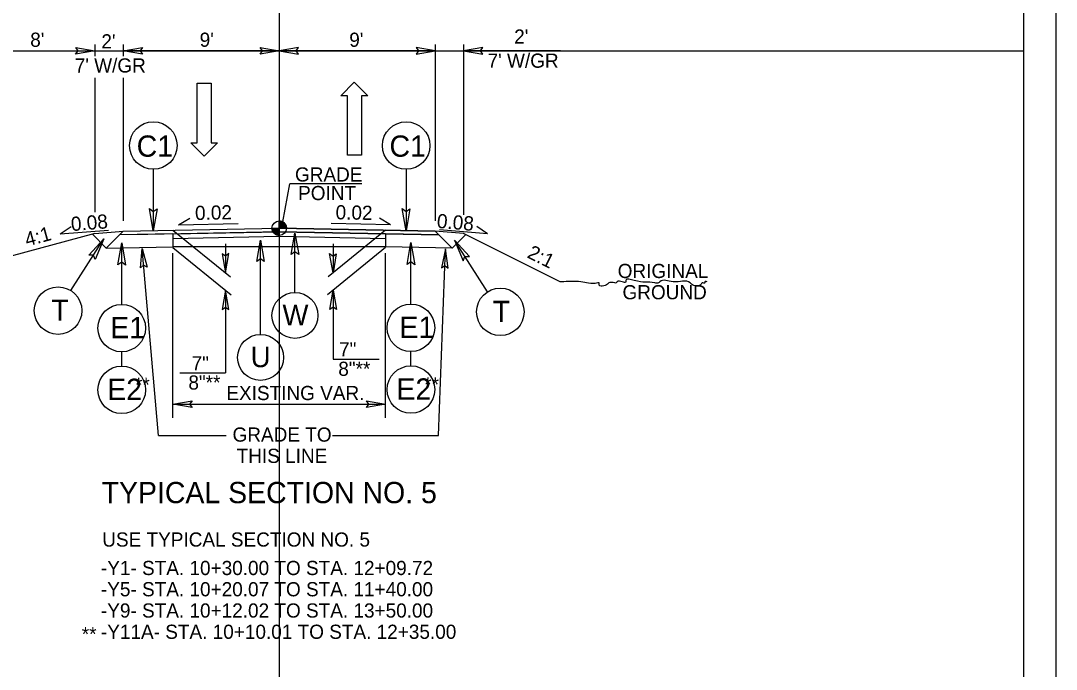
# Model space of a CAD drawing. Extents: x 18938 to 19565, y 6931 to 7973.
# Drawn here: x 19309.4 to 19382.4, y 7592.1 to 7637.9 of the extents above; entities that cross this region are included whole.
import ezdxf

# ---------------------------------------------------------------- set-up
doc = ezdxf.new("R2010")
doc.units = 0
for name, color, linetype in [('Old_Level_1', 7, 'Continuous'), ('Old_Level_11', 7, 'Continuous'), ('Old_Level_2', 7, 'Continuous'), ('Old_Level_3', 7, 'Continuous'), ('Prop Dimension', 7, 'Continuous'), ('Prop Pavement Schedule Description CELL', 7, 'Continuous'), ('Prop Shade Medium', 7, 'Continuous'), ('Prop Terminator CELL', 7, 'Continuous'), ('Sheet Data Field CELL', 7, 'Continuous'), ('Sheet Plot Border Outside CELL', 7, 'Continuous'), ('Sheet Typical CELL', 7, 'Continuous'), ('Typical Curb CELL', 7, 'Continuous'), ('Typical Detail Wedge1 CELL', 7, 'Continuous'), ('Typical Detail Wedge2 CELL', 7, 'Continuous'), ('Typical Detail Wedge3 CELL', 7, 'Continuous'), ('Typical Guardrail CELL', 7, 'Continuous'), ('Typical Hinge Slope Arterial CELL', 7, 'Continuous'), ('Typical ID Circle CELL', 7, 'Continuous'), ('Typical Pavement Slope Information CELL', 7, 'Continuous'), ('Typical Shoulder Slope Information CELL', 7, 'Continuous'), ('Typical Terminator CELL', 7, 'Continuous'), ('Typical Text General CELL', 7, 'Continuous'), ('Typical Text Grade Point CELL', 7, 'Continuous'), ('Typical Text ID Circle CELL', 7, 'Continuous')]:
    doc.layers.add(name, color=color, linetype=linetype)

msp = doc.modelspace()

# ---------------------------------------------------------------- linework, layer by layer
at = {"layer": 'Old_Level_1'}
for p, q in [((19320.158, 7622.846), (19327.659, 7622.996)), ((19327.659, 7622.996), (19335.158, 7622.846))]:
    msp.add_line(p, q, dxfattribs=at)
at = {"layer": 'Old_Level_3'}
msp.add_line((19314.658, 7635.752), (19316.658, 7635.752), dxfattribs=at)
at = {"layer": 'Prop Dimension'}
msp.add_lwpolyline([(19155.167, 7519.077), (19382.434, 7519.077), (19382.434, 7665.511), (19155.167, 7665.511)], close=True, dxfattribs=at)
at = {"layer": 'Prop Pavement Schedule Description CELL'}
for p, q in [((19315.468, 7621.836), (19314.484, 7622.82)), ((19314.658, 7622.866), (19316.658, 7623.026)), ((19315.468, 7621.836), (19316.658, 7623.026)), ((19320.158, 7622.846), (19316.403, 7622.771)), ((19316.658, 7623.026), (19327.659, 7623.246)), ((19338.658, 7623.026), (19327.658, 7623.246)), ((19335.158, 7622.846), (19338.913, 7622.771)), ((19340.658, 7622.866), (19338.658, 7623.026)), ((19339.849, 7621.836), (19338.658, 7623.026)), ((19339.849, 7621.836), (19340.806, 7622.793)), ((19347.46, 7619.466), (19340.658, 7622.866)), ((19315.468, 7621.836), (19320.158, 7621.93)), ((19320.158, 7621.934), (19320.158, 7621.93)), ((19335.158, 7621.934), (19335.158, 7621.93)), ((19339.849, 7621.836), (19335.158, 7621.93))]:
    msp.add_line(p, q, dxfattribs=at)
at = {"layer": 'Prop Shade Medium'}
msp.add_line((19314.658, 7622.866), (19306.658, 7620.717), dxfattribs=at)
at = {"layer": 'Sheet Data Field CELL'}
for points in [[(19313.308, 7635.984), (19314.658, 7635.752), (19313.301, 7635.512), (19313.473, 7635.752)], [(19313.308, 7635.984), (19314.658, 7635.752), (19313.301, 7635.512), (19313.473, 7635.752)], [(19318.008, 7635.519), (19316.658, 7635.752), (19318.016, 7635.992), (19317.843, 7635.752)], [(19326.313, 7635.984), (19327.663, 7635.752), (19326.305, 7635.512), (19326.478, 7635.752)], [(19329.013, 7635.984), (19327.663, 7635.752), (19329.02, 7635.512), (19328.848, 7635.752)], [(19337.308, 7635.519), (19338.658, 7635.752), (19337.301, 7635.992), (19337.473, 7635.752)], [(19342.008, 7635.984), (19340.658, 7635.752), (19342.016, 7635.512), (19341.843, 7635.752)], [(19317.88, 7620.452), (19317.996, 7621.817), (19318.352, 7620.485), (19318.098, 7620.636)], [(19323.635, 7621.442), (19323.868, 7620.092), (19324.108, 7621.449), (19323.868, 7621.277)], [(19331.682, 7621.442), (19331.449, 7620.092), (19331.209, 7621.449), (19331.449, 7621.277)], [(19339.559, 7620.433), (19339.377, 7621.791), (19339.087, 7620.443), (19339.333, 7620.607)], [(19324.1, 7617.518), (19323.867, 7618.868), (19323.627, 7617.511), (19323.867, 7617.683)], [(19331.217, 7617.518), (19331.449, 7618.868), (19331.689, 7617.511), (19331.449, 7617.683)], [(19321.508, 7610.596), (19320.158, 7610.829), (19321.516, 7611.069), (19321.343, 7610.829)], [(19333.808, 7611.061), (19335.158, 7610.829), (19333.801, 7610.589), (19333.973, 7610.829)]]:
    msp.add_lwpolyline(points, close=True, dxfattribs=at)
at = {"layer": 'Sheet Typical CELL'}
for p, q in [((19314.658, 7636.212), (19314.658, 7635.391)), ((19316.658, 7636.212), (19316.658, 7635.391)), ((19338.658, 7636.212), (19338.658, 7623.766)), ((19340.658, 7636.212), (19340.658, 7624.193)), ((19306.658, 7635.752), (19314.658, 7635.752)), ((19338.658, 7635.752), (19316.658, 7635.752)), ((19347.496, 7635.752), (19340.658, 7635.752)), ((19314.658, 7633.843), (19314.658, 7624.366)), ((19316.658, 7633.843), (19316.658, 7623.766)), ((19320.158, 7623.096), (19324.214, 7619.812)), ((19335.158, 7623.096), (19331.103, 7619.812)), ((19323.868, 7622.136), (19323.868, 7620.092)), ((19331.449, 7622.136), (19331.449, 7620.092)), ((19319.137, 7608.612), (19317.996, 7621.817)), ((19320.158, 7621.873), (19324.263, 7618.548)), ((19320.158, 7609.865), (19320.158, 7621.49)), ((19335.158, 7621.873), (19331.053, 7618.548)), ((19335.158, 7609.865), (19335.158, 7621.49)), ((19338.89, 7608.612), (19339.377, 7621.791)), ((19323.867, 7618.868), (19323.867, 7613.031)), ((19331.449, 7618.868), (19331.449, 7614)), ((19331.449, 7614), (19334.701, 7614)), ((19320.643, 7613.031), (19323.867, 7613.031)), ((19320.158, 7610.829), (19335.158, 7610.829)), ((19319.137, 7608.612), (19323.928, 7608.612)), ((19331.406, 7608.612), (19338.89, 7608.612))]:
    msp.add_line(p, q, dxfattribs=at)
at = {"layer": 'Typical Curb CELL'}
msp.add_spline([(19357.824, 7619.466), (19357.652, 7619.466), (19357.652, 7619.38), (19357.481, 7619.38), (19357.396, 7619.294), (19356.71, 7619.294), (19356.625, 7619.38), (19355.425, 7619.466), (19354.483, 7619.466), (19354.398, 7619.38), (19354.141, 7619.38), (19352.685, 7619.551), (19352.085, 7619.551), (19352.085, 7619.466), (19351.485, 7619.466), (19351.4, 7619.38), (19351.314, 7619.38), (19350.886, 7619.38), (19350.8, 7619.294), (19350.201, 7619.294), (19350.201, 7619.38), (19350.115, 7619.38), (19348.916, 7619.466), (19347.545, 7619.466), (19347.46, 7619.466)], degree=3, dxfattribs=at)
at = {"layer": 'Typical Detail Wedge1 CELL'}
for p, q in [((19327.659, 7623.246), (19327.659, 7623.758)), ((19327.146, 7623.246), (19327.659, 7623.246)), ((19327.658, 7622.734), (19327.659, 7623.246)), ((19327.659, 7623.246), (19327.658, 7622.734)), ((19328.17, 7623.246), (19327.659, 7623.246))]:
    msp.add_line(p, q, dxfattribs=at)
for points in [[(19327.663, 7623.758), (19327.663, 7623.758), (19327.663, 7623.246)], [(19327.674, 7623.758), (19327.673, 7623.246)], [(19327.684, 7623.758), (19327.684, 7623.246)], [(19327.694, 7623.757), (19327.694, 7623.246)], [(19327.704, 7623.756), (19327.704, 7623.246)], [(19327.715, 7623.755), (19327.715, 7623.246)], [(19327.725, 7623.754), (19327.725, 7623.246)], [(19327.735, 7623.753), (19327.735, 7623.246)], [(19327.746, 7623.751), (19327.745, 7623.246)], [(19327.756, 7623.749), (19327.756, 7623.246)], [(19327.766, 7623.747), (19327.766, 7623.246)], [(19327.776, 7623.744), (19327.776, 7623.246)], [(19327.787, 7623.742), (19327.786, 7623.246)], [(19327.797, 7623.739), (19327.797, 7623.246)], [(19327.807, 7623.736), (19327.807, 7623.246)], [(19327.817, 7623.733), (19327.817, 7623.246)], [(19327.828, 7623.73), (19327.827, 7623.246)], [(19327.838, 7623.726), (19327.837, 7623.246)], [(19327.848, 7623.722), (19327.848, 7623.246)], [(19327.858, 7623.718), (19327.858, 7623.246)], [(19327.868, 7623.713), (19327.868, 7623.246)], [(19327.878, 7623.709), (19327.878, 7623.246)], [(19327.889, 7623.704), (19327.889, 7623.246)], [(19327.899, 7623.698), (19327.899, 7623.246)], [(19327.909, 7623.693), (19327.909, 7623.246)], [(19327.919, 7623.687), (19327.919, 7623.246)], [(19327.93, 7623.681), (19327.93, 7623.246)], [(19327.94, 7623.674), (19327.94, 7623.246)], [(19327.95, 7623.667), (19327.95, 7623.246)], [(19327.961, 7623.66), (19327.961, 7623.246)], [(19327.971, 7623.652), (19327.971, 7623.246)], [(19327.981, 7623.644), (19327.981, 7623.246)], [(19327.991, 7623.635), (19327.991, 7623.246)], [(19328.002, 7623.626), (19328.001, 7623.246)], [(19328.012, 7623.617), (19328.012, 7623.246)], [(19328.022, 7623.607), (19328.022, 7623.246)], [(19328.032, 7623.596), (19328.032, 7623.246)], [(19328.042, 7623.585), (19328.042, 7623.246)], [(19328.053, 7623.573), (19328.052, 7623.246)], [(19328.063, 7623.56), (19328.063, 7623.246)], [(19328.073, 7623.547), (19328.073, 7623.246)], [(19328.083, 7623.532), (19328.083, 7623.246)], [(19328.093, 7623.516), (19328.093, 7623.246)], [(19328.104, 7623.499), (19328.104, 7623.246)], [(19328.114, 7623.48), (19328.114, 7623.246)], [(19328.124, 7623.458), (19328.124, 7623.246)], [(19328.135, 7623.435), (19328.135, 7623.246)], [(19327.149, 7623.246), (19327.149, 7623.19)], [(19327.16, 7623.246), (19327.16, 7623.13)], [(19327.17, 7623.246), (19327.17, 7623.093)], [(19327.18, 7623.246), (19327.18, 7623.063)], [(19327.19, 7623.246), (19327.19, 7623.038)], [(19327.2, 7623.246), (19327.2, 7623.017)], [(19327.211, 7623.246), (19327.211, 7622.997)], [(19327.221, 7623.246), (19327.221, 7622.98)], [(19327.231, 7623.246), (19327.231, 7622.964)], [(19327.242, 7623.246), (19327.242, 7622.949)], [(19327.252, 7623.246), (19327.252, 7622.935)], [(19327.262, 7623.246), (19327.262, 7622.922)], [(19327.272, 7623.246), (19327.272, 7622.91)], [(19327.283, 7623.246), (19327.283, 7622.898)], [(19327.293, 7623.246), (19327.293, 7622.888)], [(19327.303, 7623.246), (19327.303, 7622.878)], [(19327.313, 7623.246), (19327.313, 7622.868)], [(19327.324, 7623.246), (19327.323, 7622.859)], [(19327.334, 7623.246), (19327.334, 7622.85)], [(19327.344, 7623.246), (19327.344, 7622.842)], [(19327.354, 7623.246), (19327.354, 7622.835)], [(19327.364, 7623.246), (19327.364, 7622.827)], [(19327.375, 7623.246), (19327.374, 7622.82)], [(19327.385, 7623.246), (19327.385, 7622.813)], [(19327.395, 7623.246), (19327.395, 7622.807)], [(19327.405, 7623.246), (19327.405, 7622.801)], [(19327.415, 7623.246), (19327.415, 7622.795)], [(19327.426, 7623.246), (19327.426, 7622.79)], [(19327.436, 7623.246), (19327.436, 7622.785)], [(19327.446, 7623.246), (19327.446, 7622.78)], [(19327.457, 7623.246), (19327.457, 7622.776)], [(19327.467, 7623.246), (19327.467, 7622.772)], [(19327.477, 7623.246), (19327.477, 7622.767)], [(19327.488, 7623.246), (19327.488, 7622.764)], [(19327.498, 7623.246), (19327.498, 7622.76)], [(19327.508, 7623.246), (19327.508, 7622.757)], [(19327.518, 7623.246), (19327.518, 7622.754)], [(19327.528, 7623.246), (19327.528, 7622.751)], [(19327.539, 7623.246), (19327.538, 7622.749)], [(19327.549, 7623.246), (19327.549, 7622.746)], [(19327.559, 7623.246), (19327.559, 7622.744)], [(19327.569, 7623.246), (19327.569, 7622.742)], [(19327.579, 7623.246), (19327.579, 7622.741)], [(19327.59, 7623.246), (19327.59, 7622.739)], [(19327.6, 7623.246), (19327.6, 7622.738)], [(19327.61, 7623.246), (19327.61, 7622.736)], [(19327.62, 7623.246), (19327.62, 7622.736)], [(19327.631, 7623.246), (19327.631, 7622.735)], [(19327.641, 7623.246), (19327.641, 7622.735)], [(19327.651, 7623.246), (19327.651, 7622.734), (19327.651, 7622.734)], [(19328.145, 7623.406), (19328.145, 7623.246)], [(19328.155, 7623.371), (19328.155, 7623.246)], [(19328.165, 7623.319), (19328.165, 7623.246)]]:
    msp.add_lwpolyline(points, dxfattribs=at)
msp.add_circle((19327.658, 7623.246), 0.512, dxfattribs=at)
for start, end in [(359.99048, 89.99048), (179.99048, 269.99048)]:
    msp.add_arc((19327.658, 7623.246), 0.512, start, end, dxfattribs=at)
at = {"layer": 'Typical Detail Wedge3 CELL'}
for p, q in [((19321.865, 7629.265), (19321.865, 7633.465)), ((19321.865, 7633.465), (19322.855, 7633.465)), ((19322.855, 7633.465), (19322.855, 7629.265)), ((19332.011, 7632.594), (19332.941, 7633.539)), ((19332.941, 7633.539), (19333.901, 7632.594)), ((19332.461, 7632.594), (19332.011, 7632.594)), ((19332.461, 7628.394), (19332.461, 7632.594)), ((19333.901, 7632.594), (19333.451, 7632.594)), ((19333.451, 7632.594), (19333.451, 7628.394)), ((19322.375, 7628.32), (19321.415, 7629.265)), ((19321.415, 7629.265), (19321.865, 7629.265)), ((19323.305, 7629.265), (19322.375, 7628.32)), ((19322.855, 7629.265), (19323.305, 7629.265)), ((19333.451, 7628.394), (19332.461, 7628.394))]:
    msp.add_line(p, q, dxfattribs=at)
at = {"layer": 'Typical Guardrail CELL'}
for p, q in [((19252.244, 7635.751), (19380.142, 7635.751)), ((19327.658, 7635.751), (19327.658, 7292.693))]:
    msp.add_line(p, q, dxfattribs=at)
at = {"layer": 'Typical Hinge Slope Arterial CELL'}
for p, q in [((19316.403, 7622.771), (19316.658, 7623.026)), ((19318.403, 7622.811), (19316.403, 7622.771)), ((19316.658, 7623.026), (19327.659, 7623.246)), ((19327.659, 7622.996), (19318.403, 7622.811)), ((19318.403, 7622.811), (19318.403, 7622.811)), ((19327.659, 7623.246), (19338.658, 7623.026)), ((19338.913, 7622.771), (19327.659, 7622.996)), ((19338.658, 7623.026), (19338.913, 7622.771))]:
    msp.add_line(p, q, dxfattribs=at)
at = {"layer": 'Typical ID Circle CELL'}
for p, q in [((19320.158, 7622.846), (19320.158, 7621.934)), ((19335.158, 7622.846), (19335.158, 7621.934)), ((19320.158, 7622.528), (19327.658, 7622.678)), ((19327.658, 7622.678), (19335.158, 7622.528)), ((19335.158, 7621.934), (19320.158, 7621.934))]:
    msp.add_line(p, q, dxfattribs=at)
at = {"layer": 'Typical Pavement Slope Information CELL'}
msp.add_lwpolyline([(19380.142, 7662.503), (19177.642, 7662.503), (19177.642, 7522.088), (19380.142, 7522.088)], close=True, dxfattribs=at)
at = {"layer": 'Typical Terminator CELL'}
for p, q in [((19318.781, 7627.4), (19318.781, 7623.069)), ((19336.604, 7627.399), (19336.604, 7623.068)), ((19328.766, 7618.707), (19328.766, 7622.891)), ((19312.966, 7618.845), (19315.293, 7622.498)), ((19316.555, 7617.873), (19316.555, 7622.204)), ((19326.339, 7615.745), (19326.339, 7622.398)), ((19336.941, 7617.895), (19336.941, 7622.226)), ((19342.343, 7618.755), (19340.016, 7622.408)), ((19316.555, 7613.515), (19316.555, 7614.521)), ((19336.941, 7613.537), (19336.941, 7614.544))]:
    msp.add_line(p, q, dxfattribs=at)
for centre, radius in [((19318.781, 7629.076), 1.676), ((19336.604, 7629.074), 1.676), ((19312.066, 7617.431), 1.676), ((19328.766, 7617.088), 1.619), ((19343.243, 7617.342), 1.676), ((19316.555, 7616.197), 1.676), ((19336.941, 7616.22), 1.676), ((19326.339, 7614.126), 1.619), ((19316.555, 7611.839), 1.676), ((19336.941, 7611.861), 1.676)]:
    msp.add_circle(centre, radius, dxfattribs=at)
at = {"layer": 'Typical Text General CELL'}
for points in [[(19319.049, 7624.621), (19318.781, 7623.069), (19318.506, 7624.629), (19318.781, 7624.431)], [(19336.871, 7624.619), (19336.604, 7623.068), (19336.328, 7624.628), (19336.604, 7624.43)], [(19328.508, 7621.392), (19328.766, 7622.891), (19329.032, 7621.383), (19328.766, 7621.575)], [(19314.234, 7621.333), (19315.293, 7622.498), (19314.687, 7621.034), (19314.561, 7621.349)], [(19316.288, 7620.652), (19316.555, 7622.204), (19316.831, 7620.644), (19316.555, 7620.842)], [(19326.081, 7620.899), (19326.339, 7622.398), (19326.605, 7620.891), (19326.339, 7621.082)], [(19336.674, 7620.675), (19336.941, 7622.226), (19337.217, 7620.666), (19336.941, 7620.864)], [(19341.075, 7621.243), (19340.016, 7622.408), (19340.622, 7620.944), (19340.748, 7621.259)]]:
    msp.add_lwpolyline(points, close=True, dxfattribs=at)
at = {"layer": 'Typical Text Grade Point CELL'}
for p, q in [((19320.563, 7623.487), (19321.346, 7623.96)), ((19320.563, 7623.487), (19324.751, 7623.57)), ((19335.507, 7623.487), (19331.318, 7623.57)), ((19335.507, 7623.487), (19334.724, 7623.96)), ((19312.226, 7622.847), (19312.979, 7623.366)), ((19312.226, 7622.847), (19315.612, 7623.118)), ((19342.345, 7622.855), (19338.959, 7623.126)), ((19342.345, 7622.855), (19341.592, 7623.374))]:
    msp.add_line(p, q, dxfattribs=at)
at = {"layer": 'Typical Text ID Circle CELL'}
for p, q in [((19327.658, 7639.889), (19327.658, 7635.752)), ((19327.658, 7635.752), (19327.658, 7619.51)), ((19327.908, 7623.699), (19328.404, 7626.367)), ((19333.481, 7626.367), (19328.404, 7626.367))]:
    msp.add_line(p, q, dxfattribs=at)

# ---------------------------------------------------------------- texts
at = {"layer": 'Old_Level_11'}
for s, height, p in [('TYPICAL SECTION NO. 5', 1.5, (19315.138, 7603.846)), ('USE TYPICAL SECTION NO. 5', 1, (19315.182, 7600.782))]:
    msp.add_text(s, height=height, dxfattribs=at).set_placement(p)
at = {"layer": 'Old_Level_2'}
for s, p in [('ORIGINAL', (19351.516, 7619.729)), ('GROUND', (19351.853, 7618.229))]:
    msp.add_text(s, height=1, dxfattribs=at).set_placement(p)
at = {"layer": 'Prop Terminator CELL'}
for s, height, p in [('C1', 1.5, (19317.608, 7628.287)), ('C1', 1.5, (19335.43, 7628.286)), ('W', 1.449, (19327.887, 7616.401)), ('T', 1.5, (19342.698, 7616.622)), ('E1', 1.5, (19315.747, 7615.486)), ('E1', 1.5, (19336.133, 7615.508)), ('U', 1.449, (19325.644, 7613.439)), ('E2', 1.5, (19315.532, 7611.127)), ('E2', 1.5, (19335.919, 7611.149))]:
    msp.add_text(s, height=height, dxfattribs=at).set_placement(p)
msp.add_text('T', height=1.5, rotation=360, dxfattribs=at).set_placement((19311.597, 7616.711))
at = {"layer": 'Sheet Plot Border Outside CELL'}
for s, p in [('GRADE', (19328.769, 7626.536)), ('POINT', (19328.987, 7625.225))]:
    msp.add_text(s, height=1, rotation=0.00004, dxfattribs=at).set_placement(p)
at = {"layer": 'Sheet Typical CELL'}
for p in [(19317.491, 7611.698), (19337.877, 7611.72), (19313.738, 7594.109)]:
    msp.add_text('**', height=1, dxfattribs=at).set_placement(p)
at = {"layer": 'Typical Detail Wedge2 CELL'}
for s, p in [("8'", (19310.104, 7636.041)), ("2'", (19315.119, 7635.927)), ("9'", (19322.048, 7636.041)), ("9'", (19332.593, 7636.041)), ("2'", (19344.219, 7636.264)), ("7' W/GR", (19313.243, 7634.227)), ("7' W/GR", (19342.343, 7634.564)), ('7"', (19331.875, 7614.202)), ('7"', (19321.482, 7613.214)), ('8"**', (19331.82, 7612.828)), ('8"**', (19321.253, 7611.859)), ('EXISTING VAR.', (19323.929, 7611.118)), ('GRADE TO', (19324.365, 7608.186)), ('THIS LINE', (19324.656, 7606.686)), ('-Y1- STA. 10+30.00 TO STA. 12+09.72', (19315.089, 7598.775)), ('-Y5- STA. 10+20.07 TO STA. 11+40.00', (19315.089, 7597.275)), ('-Y9- STA. 10+12.02 TO STA. 13+50.00', (19315.089, 7595.775)), ('-Y11A- STA. 10+10.01 TO STA. 12+35.00', (19315.089, 7594.275))]:
    msp.add_text(s, height=1, dxfattribs=at).set_placement(p)
at = {"layer": 'Typical Shoulder Slope Information CELL'}
for s, rotation, p in [('4:1', 15.1346, (19309.874, 7621.942)), ('2:1', 333.43491, (19345.071, 7621.205))]:
    msp.add_text(s, height=1, rotation=rotation, dxfattribs=at).set_placement(p)
at = {"layer": 'Typical Text Grade Point CELL'}
for s, rotation, p in [('0.02', 1.14574, (19321.73, 7623.821)), ('0.02', 358.85426, (19331.622, 7623.876)), ('0.08', 4.5738, (19313.014, 7623.035)), ('0.08', 355.4262, (19338.741, 7623.268))]:
    msp.add_text(s, height=1, rotation=rotation, dxfattribs=at).set_placement(p)

doc.saveas('drawing.dxf')
